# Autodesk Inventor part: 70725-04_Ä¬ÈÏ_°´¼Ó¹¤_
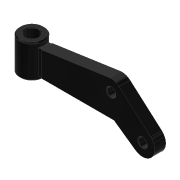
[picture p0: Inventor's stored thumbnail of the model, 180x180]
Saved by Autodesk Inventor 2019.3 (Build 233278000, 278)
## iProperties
Created: 2010-06
Part Number: 70725-04_Ä¬ÈÏ_°´¼Ó¹¤_
Material: Ogólny
Document SubType Name: Modeling
Designer: CADENGINEERING4
Density: 1 g/cm^3
Appearance: Gładki — czarny
Author: CADENGINEERING4
Revision Number: ÈÎºÎ
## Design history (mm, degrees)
feature "NONE"
feature "NONE:1"
feature "NONE:2"
feature "NONE:3"
node "Bryła1"
node "Bryła2"
node "Bryła3"
node "Bryła4"
